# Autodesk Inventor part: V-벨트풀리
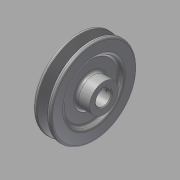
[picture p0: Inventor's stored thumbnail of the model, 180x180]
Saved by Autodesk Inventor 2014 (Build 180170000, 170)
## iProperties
Created: 2015-09
Part Number: V-벨트풀리
Material: 강철, 연강
Document SubType Name: Modeling
Designer: mduedu
Density: 7.86 g/cm^3
Mass: 779.014 g
Surface Area: 277.465 cm^2
Volume: 99.1112 cm^3
Appearance: Steel
Author: mduedu
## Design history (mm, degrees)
sketch "스케치1"
  geometry: L1 (-10, 0)-(10, 0); L2 (-10, 0)-(-10, 48); L3 (-10, 48)-(-5.976, 48); L4 (-5.976, 48)-(-2.154, 35.5); L5 (-2.154, 35.5)-(2.154, 35.5); L6 (2.154, 35.5)-(5.976, 48); L7 (5.976, 48)-(10, 48); L8 (10, 48)-(10, 0); L9 (0, 0)-(0, 35.5); L10 (-10, 43.5)-(10, 43.5); 3 further points
  constraints: 20 end point, 6 point on line, 3 perpendicular, 2 midpoint, 2 parallel, 2 symmetric about line, 1 coincident, 1 collinear, 1 equal length, 1 horizontal, 1 vertical, 1 vertical alignment
  dimensions: "d0" = 20 distance between parallel lines of L8 L2; "d2" = 96 diameter of L3 L1; "d3" = 87 diameter of L10 L1; "d4" = 4.5 distance between parallel lines of L10 L3 (derived); "d5" = 8 distance between parallel lines of L5 L10; "d6" = 9.2 distance of point (4.6, 43.5) point (-4.6, 43.5); "d7" = 34 deg angle of L6 L4
revolve "회전1" sketch "스케치1" stored, may be unused: angle "d8" = 90 deg
sketch "스케치2"
  geometry: C1 r 16 at (0, 0); 1 further point
  constraints: 1 centre point, 1 coincident
  dimensions: "d9" = 32 diameter of C1
extrude "돌출1" join sketch "스케치2" distance "d10" = 11; taper "d11" = 0 deg
fillet "모깎기1" dims "d12" = 1, "d13" = 0.5, "d14" = 2
sketch "스케치3"
  geometry: C1 r 16 at (0, 0) reference; C2 r 32 at (0, 0); 1 further point
  constraints: 1 centre point, 1 coincident
  dimensions: "d15" = 64 diameter of C2
extrude "돌출2" cut sketch "스케치3" distance "d16" = 4; taper "d17" = 0 deg
fillet "모깎기2" dims "d18" = 3
fillet "모깎기3" dims "d19" = 3
fillet "모깎기4" dims "d20" = 3
sketch "스케치4"
  geometry: C1 r 8.5 at (0, 0); 1 further point
  constraints: 1 centre point, 1 coincident
  dimensions: "d21" = 17 diameter of C1
extrude "돌출3" cut sketch "스케치4" stored distance "d22" = 4; taper "d23" = 0 deg
sketch "스케치5"
  geometry: L1 (-2.5, 8.124)-(2.5, 8.124); L2 (2.5, 8.124)-(2.5, 10.8); L3 (2.5, 10.8)-(-2.5, 10.8); L4 (-2.5, 10.8)-(-2.5, 8.124); A1 r 8.5 centre (0, 0) between (-2.5, 8.124) and (2.5, 8.124) reference; 2 further points
  constraints: 8 end point, 3 point on circle, 2 parallel, 1 horizontal, 1 perpendicular, 1 vertical alignment
  dimensions: "d24" = 5 distance of L2.end L3.end; "d26" = 19.3 distance from line of L3 point (0, -8.5)
extrude "돌출4" cut sketch "스케치5" stored distance "d27" = 4; taper "d28" = 0 deg
chamfer "모따기1" distance "d29" = 1; stored, may be unused: second distance "d30" = 2, angle "d31" = 45 deg
node "작업 평면1"
sketch "스케치6"
  geometry: L1 (-11, 16)-(-11, -16) reference; 2 further points
  constraints: 1 horizontal alignment
  dimensions: "d32" = 5 distance from line of point (-6, 0) L1
hole "구멍1" sketch "스케치6" at (-6, 0) diameter "d33" = 3.242; stored, may be unused: countersink angle "d37" = 90 deg, drill point angle "d39" = 118 deg; dims "d34" = 6, "d35" = 4, "d36" = 2, "d38" = 8
node "솔리드1"
mirror "대칭1"
